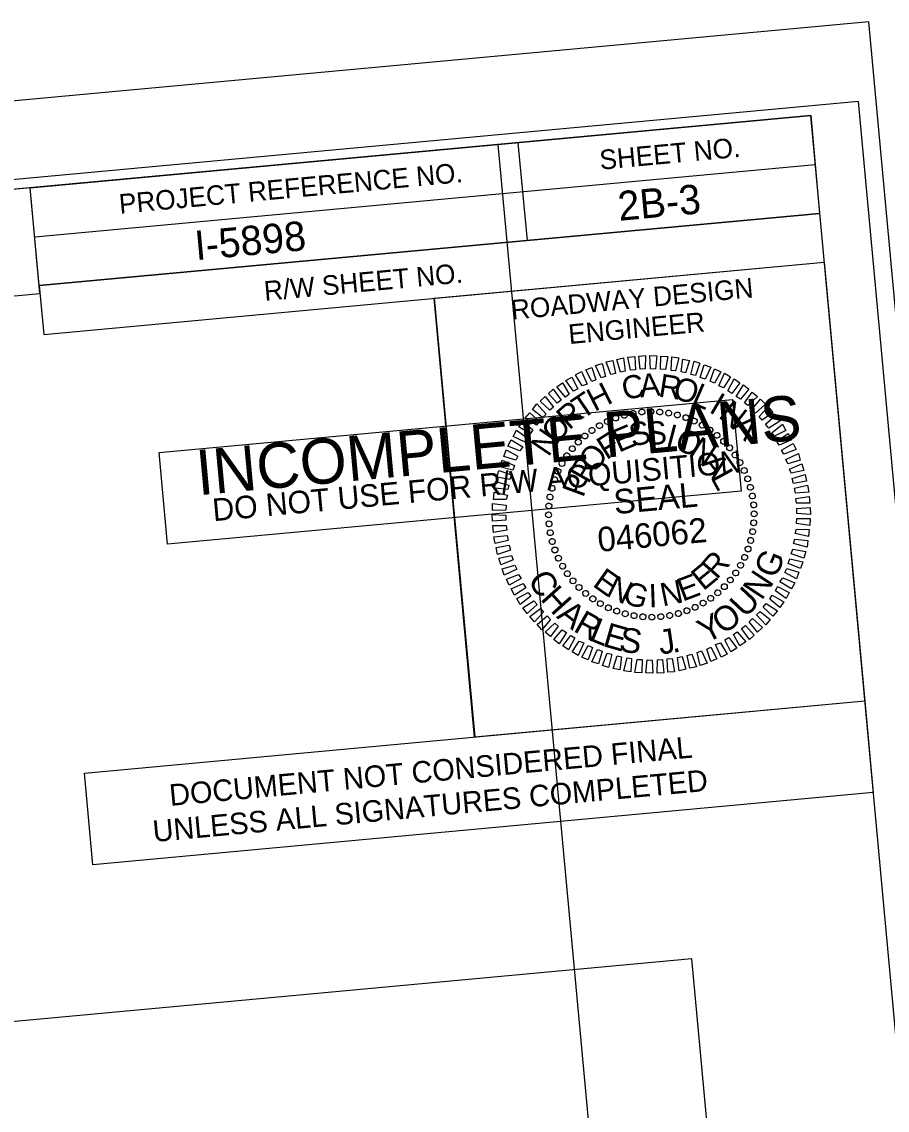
# Model space of a CAD drawing. Extents: x 1724152 to 1726026, y 971581 to 972827.
# Drawn here: x 1725612.3 to 1725833.2, y 972548.8 to 972826.6 of the extents above; entities that cross this region are included whole.
import ezdxf

# ---------------------------------------------------------------- set-up
doc = ezdxf.new("R2010")
doc.units = 0
for name, color, linetype in [('Default', 7, 'Continuous'), ('Old_Level_2', 7, 'Continuous'), ('Prop Dimension Text', 7, 'Continuous'), ('Sheet Clip Boundary CELL', 7, 'Continuous'), ('Sheet Data Field CELL', 7, 'Continuous'), ('Sheet Layout Plan Border', 7, 'Continuous'), ('Sheet Plan CELL', 7, 'Continuous'), ('Sheet Plot Border Inside CELL', 7, 'Continuous'), ('Sheet Plot Border Outside CELL', 7, 'Continuous'), ('Sheet Sticker Exception Certification CELL', 7, 'Continuous'), ('Sheet Sticker Incomplete CELL', 7, 'Continuous')]:
    doc.layers.add(name, color=color, linetype=linetype)

msp = doc.modelspace()

# ---------------------------------------------------------------- linework, layer by layer
at = {"layer": 'Old_Level_2'}
for p, q in [((1725763.82, 972725.48), (1725763.82, 972725.48)), ((1725766.07, 972726.15), (1725766.07, 972726.15)), ((1725768.27, 972726.71), (1725768.27, 972726.71)), ((1725770.55, 972727.01), (1725770.55, 972727.01)), ((1725772.85, 972727.11), (1725772.85, 972727.11)), ((1725775.13, 972726.99), (1725775.13, 972726.99)), ((1725777.36, 972726.76), (1725777.36, 972726.76)), ((1725779.62, 972726.28), (1725779.62, 972726.28)), ((1725781.81, 972725.57), (1725781.81, 972725.57)), ((1725759.72, 972723.56), (1725759.72, 972723.56)), ((1725761.71, 972724.62), (1725761.71, 972724.62)), ((1725783.95, 972724.75), (1725783.95, 972724.75)), ((1725785.96, 972723.66), (1725785.96, 972723.66)), ((1725755.97, 972720.88), (1725755.97, 972720.88)), ((1725757.81, 972722.29), (1725757.81, 972722.29)), ((1725787.93, 972722.46), (1725787.93, 972722.46)), ((1725789.72, 972721.07), (1725789.72, 972721.07)), ((1725752.75, 972717.63), (1725752.75, 972717.63)), ((1725754.29, 972719.38), (1725754.29, 972719.38)), ((1725791.47, 972719.53), (1725791.47, 972719.53)), ((1725792.97, 972717.86), (1725792.97, 972717.86)), ((1725751.37, 972715.85), (1725751.37, 972715.85)), ((1725794.38, 972716.01), (1725794.38, 972716.01)), ((1725749.07, 972711.86), (1725749.07, 972711.86)), ((1725750.16, 972713.88), (1725750.16, 972713.88)), ((1725795.64, 972714.1), (1725795.64, 972714.1)), ((1725796.7, 972712.11), (1725796.7, 972712.11)), ((1725748.25, 972709.72), (1725748.25, 972709.72)), ((1725797.57, 972710), (1725797.57, 972710)), ((1725747.55, 972707.54), (1725747.55, 972707.54)), ((1725798.23, 972707.76), (1725798.23, 972707.76)), ((1725747.06, 972705.28), (1725747.06, 972705.28)), ((1725798.79, 972705.56), (1725798.79, 972705.56)), ((1725799.1, 972703.28), (1725799.1, 972703.28)), ((1725746.71, 972700.77), (1725746.71, 972700.77)), ((1725746.83, 972703.04), (1725746.83, 972703.04)), ((1725772.95, 972700.87), (1725772.95, 972700.87)), ((1725799.19, 972700.97), (1725799.19, 972700.97)), ((1725746.81, 972698.46), (1725746.81, 972698.46)), ((1725799.07, 972698.7), (1725799.07, 972698.7)), ((1725747.11, 972696.18), (1725747.11, 972696.18)), ((1725798.85, 972696.46), (1725798.85, 972696.46)), ((1725747.67, 972693.98), (1725747.67, 972693.98)), ((1725797.65, 972692.02), (1725797.65, 972692.02)), ((1725798.36, 972694.2), (1725798.36, 972694.2)), ((1725748.34, 972691.74), (1725748.34, 972691.74)), ((1725749.2, 972689.63), (1725749.2, 972689.63)), ((1725796.84, 972689.88), (1725796.84, 972689.88)), ((1725750.27, 972687.64), (1725750.27, 972687.64)), ((1725795.74, 972687.86), (1725795.74, 972687.86)), ((1725751.53, 972685.73), (1725751.53, 972685.73)), ((1725752.94, 972683.88), (1725752.94, 972683.88)), ((1725793.16, 972684.1), (1725793.16, 972684.1)), ((1725794.54, 972685.89), (1725794.54, 972685.89)), ((1725754.44, 972682.21), (1725754.44, 972682.21)), ((1725789.94, 972680.86), (1725789.94, 972680.86)), ((1725791.62, 972682.36), (1725791.62, 972682.36)), ((1725756.19, 972680.66), (1725756.19, 972680.66)), ((1725757.97, 972679.28), (1725757.97, 972679.28)), ((1725759.95, 972678.08), (1725759.95, 972678.08)), ((1725786.18, 972678.18), (1725786.18, 972678.18)), ((1725788.1, 972679.44), (1725788.1, 972679.44)), ((1725761.96, 972676.99), (1725761.96, 972676.99)), ((1725764.1, 972676.17), (1725764.1, 972676.17)), ((1725766.28, 972675.46), (1725766.28, 972675.46)), ((1725779.84, 972675.59), (1725779.84, 972675.59)), ((1725782.08, 972676.26), (1725782.08, 972676.26)), ((1725784.2, 972677.12), (1725784.2, 972677.12)), ((1725768.55, 972674.98), (1725768.55, 972674.98)), ((1725770.78, 972674.75), (1725770.78, 972674.75)), ((1725773.06, 972674.63), (1725773.06, 972674.63)), ((1725775.36, 972674.73), (1725775.36, 972674.73)), ((1725777.64, 972675.03), (1725777.64, 972675.03))]:
    msp.add_line(p, q, dxfattribs=at)
for points in [[(1725760.17, 972735.71), (1725758.72, 972738.86), (1725760.45, 972739.42), (1725761.24, 972736.09)], [(1725762.6, 972736.55), (1725761.41, 972739.79), (1725763.1, 972740.13), (1725763.83, 972736.85)], [(1725765.07, 972737.14), (1725764.13, 972740.4), (1725765.87, 972740.81), (1725766.3, 972737.43)], [(1725767.64, 972737.69), (1725767, 972741.03), (1725768.72, 972741.17), (1725768.89, 972737.77)], [(1725770.14, 972737.91), (1725769.76, 972741.29), (1725771.48, 972741.42), (1725771.39, 972737.99)], [(1725772.75, 972738.04), (1725772.59, 972741.44), (1725774.34, 972741.32), (1725774.02, 972737.97)], [(1725775.29, 972737.9), (1725775.39, 972741.28), (1725777.14, 972741.2), (1725776.56, 972737.88)], [(1725778.01, 972737.62), (1725778.15, 972741.05), (1725779.97, 972740.83), (1725779.13, 972737.48)], [(1725780.57, 972737.22), (1725781, 972740.53), (1725782.67, 972740.18), (1725781.71, 972736.97)], [(1725783.02, 972736.54), (1725783.85, 972739.95), (1725785.38, 972739.48), (1725784.25, 972736.31)], [(1725755.3, 972733.64), (1725753.61, 972736.51), (1725755.1, 972737.3), (1725756.56, 972734.1)], [(1725757.75, 972734.76), (1725756.21, 972737.74), (1725757.77, 972738.39), (1725758.8, 972735.24)], [(1725785.46, 972735.81), (1725786.43, 972739.02), (1725788.12, 972738.47), (1725786.67, 972735.36)], [(1725787.99, 972734.88), (1725789.06, 972737.99), (1725790.72, 972737.28), (1725789.04, 972734.36)], [(1725790.17, 972733.7), (1725791.66, 972736.91), (1725793.13, 972735.97), (1725791.38, 972733.2)], [(1725751.03, 972730.81), (1725748.8, 972733.4), (1725750.32, 972734.41), (1725751.95, 972731.54)], [(1725753.13, 972732.3), (1725751.15, 972735.03), (1725752.68, 972735.93), (1725754.22, 972732.89)], [(1725792.47, 972732.37), (1725794.08, 972735.44), (1725795.56, 972734.45), (1725793.54, 972731.75)], [(1725794.62, 972730.98), (1725796.46, 972733.92), (1725797.84, 972732.81), (1725795.7, 972730.31)], [(1725747.09, 972727.48), (1725744.58, 972729.73), (1725745.86, 972730.97), (1725748, 972728.26)], [(1725748.89, 972729.26), (1725746.67, 972731.69), (1725747.92, 972732.83), (1725749.96, 972730)], [(1725796.7, 972729.37), (1725798.66, 972732.05), (1725800.05, 972730.95), (1725797.57, 972728.62)], [(1725745.18, 972725.64), (1725742.65, 972727.67), (1725743.76, 972729.06), (1725746.09, 972726.47)], [(1725798.72, 972727.7), (1725800.85, 972730.3), (1725802.1, 972729.01), (1725799.56, 972726.74)], [(1725800.5, 972725.84), (1725802.81, 972728.3), (1725803.96, 972726.91), (1725801.24, 972724.92)], [(1725743.67, 972723.63), (1725740.78, 972725.47), (1725741.95, 972726.81), (1725744.41, 972724.55)], [(1725802.09, 972723.86), (1725804.63, 972726.14), (1725805.79, 972724.69), (1725802.93, 972722.9)], [(1725742.07, 972721.45), (1725739.14, 972723.18), (1725740.14, 972724.66), (1725742.69, 972722.47)], [(1725803.69, 972721.72), (1725806.4, 972723.86), (1725807.26, 972722.32), (1725804.42, 972720.8)], [(1725739.4, 972717.06), (1725736.31, 972718.3), (1725737.19, 972719.87), (1725740.13, 972718.08)], [(1725740.73, 972719.31), (1725737.73, 972720.77), (1725738.55, 972722.38), (1725741.29, 972720.37)], [(1725804.98, 972719.6), (1725807.87, 972721.5), (1725808.73, 972719.91), (1725805.62, 972718.51)], [(1725738.4, 972714.69), (1725735.29, 972715.66), (1725735.89, 972717.36), (1725738.91, 972715.74)], [(1725806.18, 972717.26), (1725809.2, 972718.96), (1725809.95, 972717.41), (1725806.82, 972716.23)], [(1725737.62, 972712.18), (1725734.27, 972713.02), (1725734.87, 972714.72), (1725738.01, 972713.38)], [(1725807.29, 972714.86), (1725810.48, 972716.42), (1725810.98, 972714.74), (1725807.77, 972713.81)], [(1725736.83, 972709.78), (1725733.51, 972710.36), (1725734, 972712.04), (1725737.28, 972710.93)], [(1725808.19, 972712.43), (1725811.35, 972713.78), (1725811.86, 972712.05), (1725808.62, 972711.37)], [(1725736.33, 972707.2), (1725733.03, 972707.52), (1725733.21, 972709.27), (1725736.62, 972708.33)], [(1725808.93, 972709.99), (1725812.23, 972711.09), (1725812.58, 972709.34), (1725809.28, 972708.76)], [(1725735.93, 972704.63), (1725732.66, 972704.69), (1725732.83, 972706.5), (1725736.22, 972705.77)], [(1725809.52, 972707.53), (1725812.85, 972708.32), (1725813.15, 972706.56), (1725809.76, 972706.29)], [(1725735.8, 972701.93), (1725732.44, 972701.88), (1725732.46, 972703.67), (1725735.92, 972703.21)], [(1725809.85, 972704.93), (1725813.22, 972705.46), (1725813.41, 972703.7), (1725809.99, 972703.69)], [(1725735.82, 972699.41), (1725732.43, 972699.14), (1725732.34, 972700.87), (1725735.78, 972700.67)], [(1725810.09, 972702.33), (1725813.48, 972702.6), (1725813.56, 972700.87), (1725810.12, 972701.07)], [(1725736.05, 972696.8), (1725732.69, 972696.28), (1725732.5, 972698.04), (1725735.91, 972698.05)], [(1725810.1, 972699.81), (1725813.46, 972699.86), (1725813.45, 972698.07), (1725809.98, 972698.53)], [(1725736.39, 972694.21), (1725733.06, 972693.42), (1725732.76, 972695.18), (1725736.15, 972695.45)], [(1725809.98, 972697.11), (1725813.25, 972697.05), (1725813.08, 972695.24), (1725809.68, 972695.97)], [(1725736.98, 972691.75), (1725733.68, 972690.65), (1725733.33, 972692.4), (1725736.63, 972692.98)], [(1725809.07, 972691.96), (1725812.4, 972691.38), (1725811.9, 972689.69), (1725808.62, 972690.81)], [(1725809.58, 972694.54), (1725812.88, 972694.22), (1725812.7, 972692.46), (1725809.28, 972693.4)], [(1725737.72, 972689.31), (1725734.55, 972687.96), (1725734.05, 972689.69), (1725737.29, 972690.36)], [(1725808.29, 972689.56), (1725811.64, 972688.72), (1725811.04, 972687.02), (1725807.89, 972688.36)], [(1725738.62, 972686.88), (1725735.42, 972685.32), (1725734.92, 972687), (1725738.13, 972687.93)], [(1725807.51, 972687.05), (1725810.62, 972686.08), (1725810.01, 972684.38), (1725807, 972686)], [(1725739.72, 972684.48), (1725736.7, 972682.78), (1725735.95, 972684.33), (1725739.08, 972685.51)], [(1725806.51, 972684.68), (1725809.59, 972683.44), (1725808.71, 972681.87), (1725805.78, 972683.65)], [(1725740.93, 972682.14), (1725738.03, 972680.24), (1725737.18, 972681.83), (1725740.28, 972683.22)], [(1725742.21, 972680.02), (1725739.5, 972677.88), (1725738.65, 972679.42), (1725741.48, 972680.94)], [(1725805.18, 972682.43), (1725808.18, 972680.97), (1725807.36, 972679.36), (1725804.61, 972681.37)], [(1725743.82, 972677.88), (1725741.28, 972675.6), (1725740.12, 972677.05), (1725742.98, 972678.84)], [(1725802.24, 972678.11), (1725805.12, 972676.27), (1725803.95, 972674.93), (1725801.5, 972677.19)], [(1725803.84, 972680.28), (1725806.76, 972678.55), (1725805.77, 972677.08), (1725803.21, 972679.27)], [(1725745.4, 972675.9), (1725743.1, 972673.43), (1725741.94, 972674.83), (1725744.67, 972676.82)], [(1725800.72, 972676.1), (1725803.26, 972674.07), (1725802.15, 972672.68), (1725799.81, 972675.26)], [(1725747.19, 972674.04), (1725745.05, 972671.44), (1725743.81, 972672.72), (1725746.34, 972675)], [(1725749.21, 972672.37), (1725747.25, 972669.68), (1725745.86, 972670.79), (1725748.34, 972673.12)], [(1725798.82, 972674.26), (1725801.33, 972672.01), (1725800.05, 972670.77), (1725797.91, 972673.48)], [(1725751.28, 972670.76), (1725749.45, 972667.82), (1725748.06, 972668.93), (1725750.21, 972671.43)], [(1725753.44, 972669.37), (1725751.83, 972666.3), (1725750.35, 972667.29), (1725752.37, 972669.98)], [(1725794.87, 972670.93), (1725797.11, 972668.34), (1725795.59, 972667.33), (1725793.95, 972670.2)], [(1725797.02, 972672.48), (1725799.23, 972670.04), (1725797.99, 972668.91), (1725795.94, 972671.73)], [(1725755.74, 972668.04), (1725754.25, 972664.83), (1725752.78, 972665.77), (1725754.53, 972668.54)], [(1725757.92, 972666.86), (1725756.84, 972663.74), (1725755.19, 972664.46), (1725756.86, 972667.38)], [(1725788.15, 972666.98), (1725789.69, 972664), (1725788.13, 972663.35), (1725787.1, 972666.5)], [(1725790.61, 972668.1), (1725792.29, 972665.23), (1725790.8, 972664.43), (1725789.34, 972667.64)], [(1725792.78, 972669.44), (1725794.76, 972666.71), (1725793.23, 972665.81), (1725791.68, 972668.84)], [(1725760.44, 972665.93), (1725759.48, 972662.72), (1725757.79, 972663.27), (1725759.24, 972666.38)], [(1725762.89, 972665.2), (1725762.05, 972661.79), (1725760.53, 972662.26), (1725761.65, 972665.43)], [(1725765.33, 972664.52), (1725764.91, 972661.21), (1725763.24, 972661.56), (1725764.2, 972664.77)], [(1725767.9, 972664.12), (1725767.75, 972660.69), (1725765.94, 972660.91), (1725766.78, 972664.26)], [(1725780.84, 972664.6), (1725781.78, 972661.34), (1725780.04, 972660.93), (1725779.61, 972664.31)], [(1725783.3, 972665.19), (1725784.5, 972661.95), (1725782.8, 972661.61), (1725782.07, 972664.89)], [(1725785.73, 972666.03), (1725787.19, 972662.88), (1725785.46, 972662.32), (1725784.67, 972665.65)], [(1725770.61, 972663.84), (1725770.51, 972660.46), (1725768.77, 972660.53), (1725769.35, 972663.86)], [(1725773.15, 972663.7), (1725773.32, 972660.3), (1725771.57, 972660.42), (1725771.88, 972663.77)], [(1725775.77, 972663.83), (1725776.14, 972660.45), (1725774.42, 972660.32), (1725774.52, 972663.74)], [(1725778.27, 972664.05), (1725778.9, 972660.7), (1725777.18, 972660.57), (1725777.02, 972663.97)]]:
    msp.add_lwpolyline(points, close=True, dxfattribs=at)
for centre, major_axis in [((1725761.75, 972724.58), (-0.322, 0.681)), ((1725763.86, 972725.47), (-0.261, 0.706)), ((1725766.04, 972726.17), (-0.199, 0.726)), ((1725768.27, 972726.68), (-0.134, 0.741)), ((1725770.54, 972726.99), (-0.069, 0.75)), ((1725772.82, 972727.1), (-0.004, 0.753)), ((1725775.11, 972727.01), (0.062, 0.75)), ((1725777.38, 972726.72), (0.127, 0.742)), ((1725779.61, 972726.24), (0.191, 0.728)), ((1725781.8, 972725.56), (0.254, 0.709)), ((1725783.92, 972724.69), (0.315, 0.684)), ((1725757.8, 972722.28), (-0.435, 0.615)), ((1725759.73, 972723.52), (-0.38, 0.65)), ((1725785.95, 972723.65), (0.373, 0.654)), ((1725787.89, 972722.43), (0.429, 0.619)), ((1725754.31, 972719.32), (-0.535, 0.53)), ((1725755.99, 972720.88), (-0.487, 0.574)), ((1725789.71, 972721.04), (0.481, 0.579)), ((1725791.41, 972719.51), (0.53, 0.535)), ((1725752.78, 972717.63), (-0.579, 0.481)), ((1725792.96, 972717.83), (0.574, 0.487)), ((1725750.17, 972713.87), (-0.654, 0.373)), ((1725751.39, 972715.81), (-0.619, 0.429)), ((1725794.36, 972716.02), (0.615, 0.435)), ((1725795.6, 972714.1), (0.65, 0.38)), ((1725749.13, 972711.83), (-0.684, 0.315)), ((1725796.67, 972712.07), (0.681, 0.322)), ((1725748.26, 972709.72), (-0.709, 0.254)), ((1725797.55, 972709.96), (0.706, 0.261)), ((1725798.25, 972707.78), (0.726, 0.199)), ((1725747.1, 972705.29), (-0.742, 0.127)), ((1725747.59, 972707.53), (-0.728, 0.191)), ((1725798.76, 972705.55), (0.741, 0.134)), ((1725746.81, 972703.02), (-0.75, 0.062)), ((1725799.07, 972703.29), (0.75, 0.069)), ((1725746.73, 972700.74), (-0.753, -0.004)), ((1725799.18, 972701), (0.753, 0.004)), ((1725746.84, 972698.45), (-0.75, -0.069)), ((1725799.09, 972698.71), (0.75, -0.062)), ((1725747.15, 972696.19), (-0.741, -0.134)), ((1725747.65, 972693.95), (-0.726, -0.199)), ((1725798.32, 972694.21), (0.728, -0.191)), ((1725798.81, 972696.44), (0.742, -0.127)), ((1725748.35, 972691.78), (-0.706, -0.261)), ((1725797.64, 972692.02), (0.709, -0.254)), ((1725749.24, 972689.67), (-0.681, -0.322)), ((1725796.78, 972689.9), (0.684, -0.315)), ((1725750.31, 972687.64), (-0.65, -0.38)), ((1725751.54, 972685.72), (-0.615, -0.435)), ((1725794.51, 972685.93), (0.619, -0.429)), ((1725795.73, 972687.87), (0.654, -0.373)), ((1725752.95, 972683.91), (-0.574, -0.487)), ((1725793.13, 972684.11), (0.579, -0.481)), ((1725754.5, 972682.23), (-0.53, -0.535)), ((1725756.19, 972680.69), (-0.481, -0.579)), ((1725789.91, 972680.86), (0.487, -0.574)), ((1725791.59, 972682.42), (0.535, -0.53)), ((1725758.02, 972679.31), (-0.429, -0.619)), ((1725759.95, 972678.09), (-0.373, -0.654)), ((1725786.18, 972678.22), (0.38, -0.65)), ((1725788.1, 972679.46), (0.435, -0.615)), ((1725761.99, 972677.04), (-0.315, -0.684)), ((1725764.11, 972676.18), (-0.254, -0.709)), ((1725766.29, 972675.5), (-0.191, -0.728)), ((1725768.53, 972675.02), (-0.127, -0.742)), ((1725770.8, 972674.73), (-0.062, -0.75)), ((1725773.08, 972674.64), (0.004, -0.753)), ((1725775.37, 972674.75), (0.069, -0.75)), ((1725777.64, 972675.06), (0.134, -0.741)), ((1725779.87, 972675.57), (0.199, -0.726)), ((1725782.05, 972676.27), (0.261, -0.706)), ((1725784.16, 972677.15), (0.322, -0.681))]:
    msp.add_ellipse(centre, major_axis=major_axis, ratio=0.999708, dxfattribs=at)
at = {"layer": 'Prop Dimension Text'}
msp.add_lwpolyline([(1725467.52, 972743.45), (1725616.91, 972757.28), (1725614.41, 972784.23), (1725465.02, 972770.41)], close=True, dxfattribs=at)
at = {"layer": 'Sheet Clip Boundary CELL'}
msp.add_lwpolyline([(1724466.5, 971623.53), (1725860.56, 971752.51), (1725783.31, 972587.46), (1725594.85, 972570.02), (1725575.37, 972780.61), (1724369.77, 972669.06)], close=True, dxfattribs=at)
at = {"layer": 'Sheet Layout Plan Border'}
msp.add_lwpolyline([(1725733.83, 972795.27), (1725723.88, 972794.35), (1724369.77, 972669.06), (1724487.01, 971625.42), (1724638.15, 971639.41), (1724679.57, 971643.24), (1725830.66, 971749.75)], close=True, dxfattribs=at)
at = {"layer": 'Sheet Plan CELL'}
for p, q in [((1725738.9, 972795.68), (1725741.25, 972770.79)), ((1725615.56, 972771.74), (1725814.76, 972790.15)), ((1725616.72, 972759.25), (1725815.91, 972777.71)), ((1725616.72, 972759.25), (1725815.91, 972777.71)), ((1725617.87, 972746.82), (1725817.06, 972765.26)), ((1725616.72, 972759.25), (1725617.87, 972746.82)), ((1725717.5, 972756.04), (1725727.87, 972644.05))]:
    msp.add_line(p, q, dxfattribs=at)
for points in [[(1725813.64, 972802.65), (1724319.98, 972664.46), (1724416.72, 971618.92), (1725910.35, 971757.12)], [(1725614.41, 972784.23), (1725813.64, 972802.65), (1725815.91, 972777.71), (1725616.72, 972759.25)], [(1725717.5, 972756.04), (1725817.06, 972765.26), (1725827.44, 972653.23), (1725727.86, 972644)]]:
    msp.add_lwpolyline(points, close=True, dxfattribs=at)
at = {"layer": 'Sheet Plot Border Inside CELL'}
msp.add_lwpolyline([(1724264.11, 971602.28), (1725923.01, 971755.78), (1725825.83, 972806.28), (1724166.92, 972652.79)], close=True, dxfattribs=at)
at = {"layer": 'Sheet Plot Border Outside CELL'}
msp.add_lwpolyline([(1724253.01, 971581.17), (1725929.35, 971736.27), (1725828.47, 972826.61), (1724152.13, 972671.51)], close=True, dxfattribs=at)
at = {"layer": 'Sheet Sticker Exception Certification CELL'}
for p, q in [((1725628.25, 972634.81), (1725827.44, 972653.24)), ((1725827.44, 972653.23), (1725829.6, 972629.83)), ((1725630.42, 972611.41), (1725628.25, 972634.81)), ((1725829.6, 972629.84), (1725630.42, 972611.41))]:
    msp.add_line(p, q, dxfattribs=at)
at = {"layer": 'Sheet Sticker Incomplete CELL'}
msp.add_lwpolyline([(1725649.49, 972693.25), (1725647.33, 972716.65), (1725793.7, 972730.2), (1725795.87, 972706.8)], close=True, dxfattribs=at)

# ---------------------------------------------------------------- texts
at = {"layer": 'Default'}
for s, rotation, p in [('G', 67.086, (1725804.73, 972684.23)), ('N', 56.515, (1725801.14, 972678.68)), ('C', 302.486, (1725741.24, 972684.15)), ('H', 311.9298, (1725744.41, 972679.17)), ('U', 46.7209, (1725796.96, 972674.21)), ('A', 321.7696, (1725748.54, 972674.61)), ('R', 330.4823, (1725752.8, 972671.21)), ('Y', 27.5287, (1725786.87, 972667.8)), ('O', 35.3275, (1725791.23, 972670)), ('L', 337.8545, (1725756.77, 972668.87)), ('E', 344.0386, (1725760.31, 972667.31)), ('S', 351.0453, (1725764.49, 972666.01)), ('J', 8.3183, (1725775.22, 972665.07)), ('.', 13.5002, (1725778.44, 972665.42))]:
    msp.add_text(s, height=6.27, rotation=rotation, dxfattribs=at).set_placement(p)
at = {"layer": 'Old_Level_2'}
for s, height, rotation, p in [('C', 5.9, 12.5061, (1725766.12, 972729.94)), ('A', 5.9, 5.3065, (1725770.19, 972730.71)), ('R', 5.9, 350.9073, (1725774.58, 972730.98)), ('H', 5.9, 26.9057, (1725758.45, 972726.99)), ('O', 5.9, 343.7074, (1725778.15, 972730.58)), ('L', 5.9, 336.5071, (1725782.93, 972729.17)), ('T', 5.9, 34.106, (1725755.26, 972724.91)), ('I', 5.9, 329.3063, (1725787.42, 972727.13)), ('R', 5.9, 41.3067, (1725751.98, 972722.23)), ('N', 5.9, 322.1051, (1725789.83, 972725.77)), ('O', 5.9, 48.5079, (1725748.75, 972718.61)), ('A', 5.9, 314.9033, (1725793.24, 972723.04)), ('N', 5.9, 55.7097, (1725746.69, 972715.34)), ('E', 5.9, 22.8973, (1725764.65, 972716.58)), ('S', 5.9, 13.5418, (1725768.11, 972718.06)), ('S', 5.9, 4.1866, (1725771.85, 972718.53)), ('I', 5.9, 345.4758, (1725776.4, 972718.29)), ('O', 5.9, 336.1197, (1725778.56, 972717.79)), ('F', 5.9, 32.2532, (1725761.49, 972714.65)), ('N', 5.9, 326.7628, (1725782.27, 972716.1)), ('O', 5.9, 50.9674, (1725758.4, 972711.21)), ('R', 5.9, 60.3258, (1725756.86, 972708.46)), ('A', 5.9, 308.0465, (1725785.53, 972713.72)), ('L', 5.9, 298.687, (1725787.95, 972710.36)), ('P', 5.9, 69.6851, (1725755.56, 972704.95)), ('SEAL', 6.273, 5.2862, (1725763.64, 972700.9)), ('046062', 6.275, 5.2862, (1725759.53, 972691.27)), ('R', 5.9, 48.7676, (1725789.64, 972684.03)), ('E', 5.9, 324.5631, (1725757.7, 972682.72)), ('E', 5.9, 39.4103, (1725786.22, 972681.18)), ('N', 5.9, 333.9201, (1725761.13, 972680.26)), ('N', 5.9, 11.3426, (1725775.86, 972677.36)), ('E', 5.9, 20.6979, (1725780.94, 972678.55)), ('G', 5.9, 343.2764, (1725765.33, 972678.36)), ('I', 5.9, 1.9874, (1725772.36, 972677.13))]:
    msp.add_text(s, height=height, rotation=rotation, dxfattribs=at).set_placement(p)
at = {"layer": 'Sheet Data Field CELL'}
for s, p in [('2B-3', (1725764.76, 972775.79)), ('  I-5898 ', (1725651.21, 972765.22))]:
    msp.add_text(s, height=7.5, rotation=5.2862, dxfattribs=at).set_placement(p)
at = {"layer": 'Sheet Plan CELL'}
for s, height, p in [('SHEET NO.', 5, (1725759.97, 972788.83)), ('PROJECT REFERENCE NO.', 5.0001, (1725637.32, 972777.59)), ('R/W SHEET NO.', 5.0001, (1725674.33, 972755.36)), ('ROADWAY DESIGN', 5.0001, (1725737.4, 972750.56)), ('ENGINEER', 5, (1725752.02, 972744.34))]:
    msp.add_text(s, height=height, rotation=5.2862, dxfattribs=at).set_placement(p)
at = {"layer": 'Sheet Sticker Exception Certification CELL'}
for s, p in [('DOCUMENT NOT CONSIDERED FINAL', (1725650.18, 972626.45)), ('UNLESS ALL SIGNATURES COMPLETED', (1725645.95, 972617.22))]:
    msp.add_text(s, height=5.5, rotation=5.2862, dxfattribs=at).set_placement(p)
at = {"layer": 'Sheet Sticker Incomplete CELL'}
for s, height, p in [('INCOMPLETE PLANS', 11.52, (1725657.33, 972705.73)), ('DO NOT USE FOR R/W ACQUISITION', 5.76, (1725661.2, 972699.11))]:
    msp.add_text(s, height=height, rotation=5.2862, dxfattribs=at).set_placement(p)

doc.saveas('drawing.dxf')
